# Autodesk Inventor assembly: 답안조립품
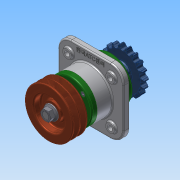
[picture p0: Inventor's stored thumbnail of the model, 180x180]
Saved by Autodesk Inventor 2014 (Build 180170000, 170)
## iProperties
Created: 2015-09
Part Number: 답안조립품
Document SubType Name: Assembly
Designer: study
Author: study
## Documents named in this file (12)
- C:\Users\study\Desktop\450909V1008\답안조립품.iam
- C:\Users\study\Desktop\450909V1008\1-본체.ipt
- C:\Users\study\Desktop\450909V1008\3-축.ipt
- C:\Users\study\Desktop\450909V1008\11-키 6x6.ipt
- C:\Users\study\Desktop\450909V1008\7-부시.ipt
- C:\Users\study\Desktop\450909V1008\6-베어링 6206.ipt
- C:\Users\study\Desktop\450909V1008\2-커버.ipt
- C:\Users\study\Desktop\450909V1008\8-오일실 30x42.ipt
- C:\Users\study\Desktop\450909V1008\10-M6.ipt
- C:\Users\study\Desktop\450909V1008\4-V벨트풀리.ipt
- C:\Users\study\Desktop\450909V1008\5-체인 스프로킷.ipt
- C:\Users\study\Desktop\450909V1008\9-M16-너트.ipt
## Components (23 placed, 11 different names)
1. 1-본체:1
2. 3-축:1 — 각도:1, 각도:2, 각도:5, 각도:6
3. 11-키 6x6:1 — 각도:1, 각도:3
4. 11-키 6x6:2 — 각도:2, 각도:4
5. 7-부시:1
6. 6-베어링 6206:1
7. 6-베어링 6206:2
8. 2-커버:1
9. 8-8-오일실 30x42:1
10. 2-커버:2
11. 8-8-오일실 30x42:2
12. 4-V벨트풀리:1 — 각도:3
13. 5-체인 스프로킷:1 — 각도:4
14. 9-M16 너트:1 — 각도:5
15. 9-M16 너트:2 — 각도:6
16. 10-M6:2
17. 10-M6:3
18. 10-M6:4
19. 10-M6:5
20. 10-M6:1
21. 10-M6:6
22. 10-M6:7
23. 10-M6:8
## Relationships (6: Angle 6)
- 각도:1 [Angle]: 3-축:1 ↔ 11-키 6x6:1
- 각도:2 [Angle]: 3-축:1 ↔ 11-키 6x6:2
- 각도:3 [Angle]: 11-키 6x6:1 ↔ 4-V벨트풀리:1
- 각도:4 [Angle]: 11-키 6x6:2 ↔ 5-체인 스프로킷:1
- 각도:5 [Angle]: 3-축:1 ↔ 9-M16 너트:1
- 각도:6 [Angle]: 3-축:1 ↔ 9-M16 너트:2
